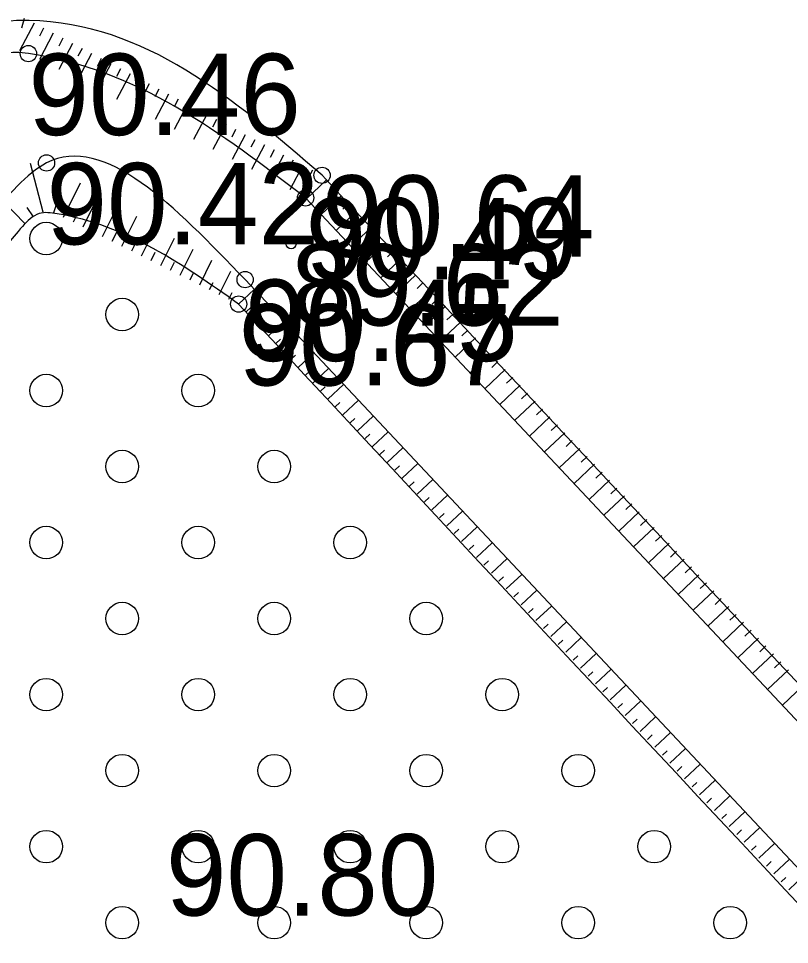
# Model space of a CAD drawing. Extents: x 316000 to 728450, y 314368 to 726000.
# Drawn here: x 725730.72 to 725766.23, y 315597.5 to 315640.13 of the extents above; entities that cross this region are included whole.
import ezdxf

# ---------------------------------------------------------------- set-up
doc = ezdxf.new("R2010")
doc.units = 0
for name, color, linetype in [('HIDG_ELEM_####_####_#', 7, 'Continuous'), ('HIDG_GRAV_####_####_#', 7, 'Continuous'), ('RELJ_AATZ_####_TKST_#', 7, 'Continuous'), ('RELJ_ELEM_####_####_#', 7, 'Continuous'), ('RELJ_NOGA_####_####_#', 7, 'Continuous'), ('TERT_ELEM_####_####_#', 7, 'Continuous')]:
    doc.layers.add(name, color=color, linetype=linetype)

msp = doc.modelspace()

# ---------------------------------------------------------------- linework, layer by layer
at = {"layer": 'HIDG_ELEM_####_####_#'}
msp.add_circle((725743.279, 315629.745), 0.225, dxfattribs=at)
at = {"layer": 'HIDG_GRAV_####_####_#'}
for points in [[(726259.175, 315086.515), (726260.768, 315088.859), (726179.005, 315175.766), (726127.8590000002, 315229.05600000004), (726063.0550000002, 315296.073), (725998.338, 315364.31700000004), (725936.648, 315430.32), (725875.3450000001, 315494.08300000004), (725809.436, 315562.19200000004), (725743.944, 315631.872)], [(725741.1610000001, 315628.109), (725806.0620000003, 315558.993), (725870.895, 315491.87100000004), (725934.12, 315427.077), (725995.775, 315361.63200000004), (726059.846, 315293.396), (726126.03, 315226.728), (726194.4910000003, 315154.86), (726259.1750000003, 315086.515)]]:
    msp.add_lwpolyline(points, dxfattribs=at)
for points in [[(725743.944, 315631.872), (725731.1800000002, 315638.5140000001), (725730.0588248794, 315638.4860084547), (725729.0416291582, 315637.5281018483), (725728.0741186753, 315636.1890738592), (725727.1019992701, 315635.017718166), (725611.6787771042, 315529.82054677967)], [(725741.1610000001, 315628.109), (725732.013, 315633.48000000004), (725729.3674430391, 315630.93907173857), (725612.6699933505, 315527.51301727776), (725555.2138402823, 315474.3075427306)]]:
    msp.add_spline(points, degree=3, dxfattribs=at)
at = {"layer": 'RELJ_ELEM_####_####_#'}
for centre in [(725731.18, 315638.514), (725732.013, 315633.48000000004), (725744.701, 315632.911), (725743.944, 315631.87200000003), (725741.1610000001, 315628.109), (725740.8620000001, 315626.984)]:
    msp.add_circle(centre, 0.375, dxfattribs=at)
at = {"layer": 'RELJ_NOGA_####_####_#'}
for p, q in [((725731.4387330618, 315639.91901510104), (725730.7655485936, 315638.6450520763)), ((725730.9867285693, 315640.1303772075), (725730.8541698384, 315639.6851369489)), ((725732.3228841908, 315639.4518140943), (725731.6877181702, 315638.24979880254)), ((725731.8808086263, 315639.6854145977), (725731.6898164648, 315639.3239728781)), ((725733.2070353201, 315638.98461308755), (725732.5748183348, 315637.7881786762)), ((725732.7649597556, 315639.2182135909), (725732.5748523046, 315638.8584461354)), ((725733.6491108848, 315638.7510125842), (725733.4598881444, 315638.39291939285)), ((725734.0911864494, 315638.51741208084), (725733.4619184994, 315637.32655854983)), ((725734.5332620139, 315638.2838115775), (725734.3449239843, 315637.9273926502)), ((725734.9753375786, 315638.05021107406), (725734.349018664, 315636.8649384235)), ((725735.4174131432, 315637.8166105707), (725735.2299598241, 315637.46186590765)), ((725735.8594887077, 315637.5830100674), (725735.2361188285, 315636.40331829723)), ((725736.3015642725, 315637.349409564), (725736.114995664, 315636.99633916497)), ((725736.743639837, 315637.11580906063), (725736.1232189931, 315635.94169817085)), ((725737.1857154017, 315636.8822085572), (725737.0000315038, 315636.5308124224)), ((725737.6277909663, 315636.6486080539), (725737.0103191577, 315635.4800780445)), ((725738.0698665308, 315636.41500755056), (725737.8850673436, 315636.06528567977)), ((725738.5119420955, 315636.18140704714), (725737.8974193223, 315635.01845791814)), ((725738.9540176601, 315635.9478065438), (725738.7701031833, 315635.59975893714)), ((725739.3960932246, 315635.7142060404), (725738.7845194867, 315634.55683779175)), ((725739.8381687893, 315635.4806055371), (725739.6551390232, 315635.1342321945)), ((725740.2802443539, 315635.2470050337), (725739.6716196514, 315634.0952176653)), ((725740.7223199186, 315635.0134045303), (725740.5401748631, 315634.6687054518)), ((725741.1643954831, 315634.77980402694), (725740.5587198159, 315633.63359753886)), ((725741.6064710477, 315634.5462035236), (725741.4252107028, 315634.20317870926)), ((725742.0485466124, 315634.3126030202), (725741.4458199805, 315633.1719774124)), ((725742.490622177, 315634.07900251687), (725742.3102465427, 315633.73765196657)), ((725742.9326977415, 315633.84540201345), (725742.3329201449, 315632.71035728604)), ((725731.8567331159, 315631.2111052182), (725731.2755291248, 315633.45294873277)), ((725743.3747733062, 315633.6118015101), (725743.1952823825, 315633.27212522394)), ((725743.8168488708, 315633.37820100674), (725743.2200203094, 315632.2487371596)), ((725744.2589244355, 315633.1446005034), (725744.0803182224, 315632.80659848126)), ((725732.8026071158, 315630.98976913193), (725733.5823610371, 315632.5585922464)), ((725744.9022320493, 315632.6976989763), (725743.983013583, 315631.8304916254)), ((725744.701, 315632.911), (725744.700532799, 315632.9101158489)), ((725745.2453464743, 315632.33400612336), (725744.9693772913, 315632.07365179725)), ((725731.0255166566, 315630.67487591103), (725729.9985763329, 315631.7343684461)), ((725732.349991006, 315631.20106889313), (725732.5172724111, 315631.72717694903)), ((725733.6980952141, 315630.5446836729), (725734.4468087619, 315632.05105521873)), ((725745.5884608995, 315631.9703132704), (725744.667884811, 315631.10182511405)), ((725731.40845525, 315630.9954562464), (725731.1165945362, 315631.4271271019)), ((725733.250351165, 315630.7672264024), (725733.4796212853, 315631.22850560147)), ((725734.5935833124, 315630.0995982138), (725735.3112564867, 315631.5435181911)), ((725746.2746897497, 315631.2429275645), (725745.3527560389, 315630.37315860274)), ((725745.9315753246, 315631.60662041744), (725745.6551988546, 315631.3458818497)), ((725735.4890714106, 315629.6545127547), (725736.1757042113, 315631.03598116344)), ((725746.6178041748, 315630.8792347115), (725746.3410204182, 315630.6181119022)), ((725734.1458392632, 315630.3221409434), (725734.3657972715, 315630.7646846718)), ((725736.3845595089, 315629.2094272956), (725737.040151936, 315630.52844413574)), ((725746.9609185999, 315630.51554185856), (725746.0376272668, 315629.6444920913)), ((725735.0413273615, 315629.8770554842), (725735.2519732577, 315630.30086374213)), ((725737.280047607, 315628.76434183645), (725737.9045996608, 315630.020907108)), ((725747.3040330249, 315630.15184900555), (725747.0268419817, 315629.89034195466)), ((725735.9368154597, 315629.4319700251), (725736.138149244, 315629.83704281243)), ((725747.64714745, 315629.7881561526), (725746.7224984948, 315628.91582558)), ((725736.832303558, 315628.986884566), (725737.0243252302, 315629.3732218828)), ((725738.1755357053, 315628.3192563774), (725738.7690473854, 315629.51337008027)), ((725747.9902618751, 315629.4244632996), (725747.7126635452, 315629.16257200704)), ((725737.7277916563, 315628.5417991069), (725737.9105012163, 315628.9094009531)), ((725739.0710238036, 315627.87417091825), (725739.6334951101, 315629.00583305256)), ((725748.3333763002, 315629.06077044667), (725747.4073697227, 315628.18715906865)), ((725748.6764907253, 315628.6970775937), (725748.3984851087, 315628.4348020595)), ((725738.6232797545, 315628.0967136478), (725738.7966772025, 315628.4455800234)), ((725739.9665119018, 315627.42908545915), (725740.4979428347, 315628.49829602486)), ((725749.0196051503, 315628.33338474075), (725748.0922409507, 315627.4584925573)), ((725739.5187678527, 315627.6516281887), (725739.6828531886, 315627.9817590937)), ((725749.3627195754, 315627.9696918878), (725749.0843066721, 315627.70703211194)), ((725740.414255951, 315627.2065427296), (725740.5690291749, 315627.517938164)), ((725740.8620000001, 315626.984), (725741.5822104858, 315627.66043396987)), ((725749.7058340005, 315627.60599903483), (725748.7771121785, 315626.7298260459)), ((725740.8620000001, 315626.984), (725740.8624450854, 315626.98489548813)), ((725750.0489484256, 315627.2423061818), (725749.7701282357, 315626.9792621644)), ((725741.204303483, 315626.6195437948), (725741.4203549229, 315626.8224629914)), ((725741.5466069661, 315626.25508758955), (725742.2667394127, 315626.93144826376)), ((725750.3920628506, 315626.87861332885), (725749.4619834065, 315626.00115953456)), ((725742.2312139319, 315625.52617517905), (725742.9512683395, 315626.20246255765)), ((725751.0782917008, 315626.15122762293), (725750.1468546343, 315625.27249302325)), ((725750.7351772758, 315626.51492047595), (725750.4559497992, 315626.25149221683)), ((725741.888910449, 315625.89063138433), (725742.104938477, 315626.09352859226)), ((725751.4214061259, 315625.78753477), (725751.1417713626, 315625.5237222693)), ((725742.573517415, 315625.16171897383), (725742.7895220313, 315625.3645941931)), ((725742.915820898, 315624.7972627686), (725743.6357972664, 315625.4734768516)), ((725751.764520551, 315625.423841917), (725750.8317258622, 315624.54382651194)), ((725752.107634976, 315625.06014906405), (725751.8275929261, 315624.79595232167)), ((725743.258124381, 315624.4328065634), (725743.4741055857, 315624.6356597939)), ((725743.6004278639, 315624.06835035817), (725744.3203261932, 315624.7444911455)), ((725752.4507494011, 315624.69645621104), (725751.5165970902, 315623.8151600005)), ((725744.28503483, 315623.33943794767), (725745.0048551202, 315624.01550543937)), ((725752.7938638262, 315624.3327633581), (725752.5134144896, 315624.0681823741)), ((725743.9427313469, 315623.70389415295), (725744.1586891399, 315623.9067253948)), ((725753.1369782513, 315623.9690705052), (725752.2014683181, 315623.0864934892)), ((725753.4800926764, 315623.60537765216), (725753.1992360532, 315623.34041242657)), ((725744.6273383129, 315622.97498174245), (725744.8432726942, 315623.1777909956)), ((725744.969641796, 315622.6105255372), (725745.6893840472, 315623.28651973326)), ((725753.8232071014, 315623.2416847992), (725752.8863395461, 315622.35782697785)), ((725754.1663215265, 315622.87799194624), (725753.8850576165, 315622.612642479)), ((725745.3119452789, 315622.246069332), (725745.5278562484, 315622.4488565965)), ((725745.6542487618, 315621.8816131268), (725746.373912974, 315622.55753402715)), ((725754.5094359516, 315622.5142990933), (725753.571210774, 315621.6291604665)), ((725754.8525503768, 315622.15060624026), (725754.5708791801, 315621.8848725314)), ((725745.9965522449, 315621.51715692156), (725746.2124398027, 315621.7199221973)), ((725746.3388557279, 315621.1527007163), (725747.058441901, 315621.82854832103)), ((725755.1956648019, 315621.7869133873), (725754.256082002, 315620.9004939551)), ((725755.538779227, 315621.4232205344), (725755.2567007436, 315621.1571025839)), ((725747.0234626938, 315620.42378830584), (725747.7429708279, 315621.099562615)), ((725755.881893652, 315621.05952768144), (725754.9409532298, 315620.17182744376)), ((725746.6811592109, 315620.78824451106), (725746.897023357, 315620.99098779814)), ((725756.2250080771, 315620.6958348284), (725755.942522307, 315620.4293326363)), ((725747.3657661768, 315620.0593321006), (725747.5816069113, 315620.262053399)), ((725747.7080696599, 315619.6948758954), (725748.4274997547, 315620.37057690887)), ((725756.5681225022, 315620.33214197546), (725755.6258244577, 315619.4431609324)), ((725756.9112369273, 315619.9684491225), (725756.6283438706, 315619.70156268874)), ((725748.0503731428, 315619.3304196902), (725748.2661904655, 315619.53311899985)), ((725748.3926766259, 315618.9659634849), (725749.1120286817, 315619.64159120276)), ((725757.2543513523, 315619.60475626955), (725756.3106956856, 315618.71449442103)), ((725749.0772835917, 315618.23705107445), (725749.7965576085, 315618.91260549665)), ((725757.9405802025, 315618.8773705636), (725756.9955669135, 315617.9858279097)), ((725757.5974657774, 315619.2410634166), (725757.3141654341, 315618.9737927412)), ((725748.7349801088, 315618.6015072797), (725748.9507740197, 315618.8041846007)), ((725758.2836946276, 315618.51367771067), (725757.9999869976, 315618.2460227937)), ((725749.4195870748, 315617.8725948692), (725749.635357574, 315618.0752502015)), ((725749.7618905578, 315617.50813866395), (725750.4810865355, 315618.1836197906)), ((725758.6268090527, 315618.14998485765), (725757.6804381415, 315617.25716139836)), ((725758.9699234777, 315617.7862920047), (725758.685808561, 315617.5182528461)), ((725750.1041940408, 315617.1436824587), (725750.3199411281, 315617.3463158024)), ((725750.4464975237, 315616.7792262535), (725751.1656154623, 315617.45463408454)), ((725759.3130379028, 315617.42259915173), (725758.3653093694, 315616.528494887)), ((725759.656152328, 315617.0589062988), (725759.3716301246, 315616.79048289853)), ((725750.7888010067, 315616.4147700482), (725751.0045246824, 315616.61738140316)), ((725751.1311044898, 315616.050313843), (725751.8501443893, 315616.7256483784)), ((725759.9992667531, 315616.6952134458), (725759.0501805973, 315615.79982837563)), ((725760.3423811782, 315616.33152059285), (725760.057451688, 315616.062712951)), ((725751.4734079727, 315615.6858576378), (725751.6891082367, 315615.888447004)), ((725751.8157114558, 315615.32140143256), (725752.5346733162, 315615.99666267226)), ((725760.6854956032, 315615.9678277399), (725759.7350518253, 315615.07116186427)), ((725761.0286100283, 315615.6041348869), (725760.7432732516, 315615.3349430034)), ((725752.1580149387, 315614.95694522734), (725752.3736917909, 315615.15951260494)), ((725752.5003184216, 315614.5924890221), (725753.219202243, 315615.2676769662)), ((725761.3717244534, 315615.2404420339), (725760.4199230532, 315614.34249535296)), ((725761.7148388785, 315614.87674918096), (725761.429094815, 315614.6071730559)), ((725752.8426219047, 315614.22803281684), (725753.0582753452, 315614.43057820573)), ((725753.1849253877, 315613.8635766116), (725753.9037311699, 315614.53869126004)), ((725762.0579533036, 315614.51305632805), (725761.1047942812, 315613.6138288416)), ((725753.8695323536, 315613.1346642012), (725754.5882600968, 315613.80970555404)), ((725762.7441821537, 315613.7856706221), (725761.789665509, 315612.88516233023)), ((725762.4010677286, 315614.14936347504), (725762.1149163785, 315613.8794031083)), ((725753.5272288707, 315613.4991204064), (725753.7428588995, 315613.7016438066)), ((725763.0872965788, 315613.4219777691), (725762.8007379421, 315613.15163316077)), ((725754.2118358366, 315612.77020799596), (725754.4274424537, 315612.97270940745)), ((725754.5541393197, 315612.40575179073), (725755.2727890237, 315613.0807198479)), ((725763.4304110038, 315613.05828491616), (725762.474536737, 315612.1564958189)), ((725763.773525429, 315612.69459206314), (725763.4865595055, 315612.42386321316)), ((725754.8964428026, 315612.04129558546), (725755.1120260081, 315612.24377500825)), ((725755.2387462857, 315611.67683938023), (725755.9573179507, 315612.35173414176)), ((725764.116639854, 315612.3308992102), (725763.1594079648, 315611.42782930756)), ((725755.9233532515, 315610.9479269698), (725756.6418468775, 315611.62274843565)), ((725764.4597542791, 315611.9672063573), (725764.172381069, 315611.69609326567)), ((725755.5810497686, 315611.312383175), (725755.7966095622, 315611.51484060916)), ((725764.8028687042, 315611.60351350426), (725763.8442791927, 315610.6991627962)), ((725765.1459831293, 315611.2398206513), (725764.8582026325, 315610.96832331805)), ((725756.2656567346, 315610.58347076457), (725756.4811931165, 315610.78590620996)), ((725756.6079602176, 315610.21901455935), (725757.3263758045, 315610.89376272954)), ((725765.4890975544, 315610.87612779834), (725764.5291504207, 315609.97049628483)), ((725765.8322119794, 315610.5124349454), (725765.544024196, 315610.2405533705)), ((725756.9502637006, 315609.85455835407), (725757.1657766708, 315610.05697181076)), ((725757.2925671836, 315609.49010214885), (725758.0109047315, 315610.1647770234)), ((725766.1753264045, 315610.14874209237), (725765.2140216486, 315609.24182977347)), ((725757.6348706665, 315609.1256459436), (725757.8503602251, 315609.3280374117)), ((725757.9771741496, 315608.7611897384), (725758.6954336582, 315609.4357913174)), ((725766.8615552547, 315609.4213563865), (725765.8988928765, 315608.51316326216)), ((725758.6617811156, 315608.03227732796), (725759.3799625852, 315608.7068056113)), ((725758.3194776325, 315608.3967335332), (725758.5349437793, 315608.5991030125)), ((725759.0040845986, 315607.6678211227), (725759.2195273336, 315607.8701686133)), ((725759.3463880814, 315607.30336491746), (725760.064491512, 315607.9778199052)), ((725759.6886915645, 315606.93890871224), (725759.9041108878, 315607.1412342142)), ((725760.0309950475, 315606.57445250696), (725760.749020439, 315607.24883419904)), ((725760.7156020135, 315605.8455400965), (725761.4335493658, 315606.5198484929)), ((725760.3732985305, 315606.20999630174), (725760.5886944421, 315606.41229981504)), ((725761.0579054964, 315605.4810838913), (725761.2732779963, 315605.6833654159)), ((725761.4002089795, 315605.116627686), (725762.1180782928, 315605.7908627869)), ((725761.7425124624, 315604.7521714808), (725761.9578615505, 315604.9544310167)), ((725762.0848159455, 315604.3877152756), (725762.8026072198, 315605.06187708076)), ((725762.4271194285, 315604.02325907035), (725762.6424451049, 315604.22549661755)), ((725762.7694229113, 315603.65880286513), (725763.4871361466, 315604.3328913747)), ((725763.4540298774, 315602.92989045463), (725764.1716650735, 315603.60390566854)), ((725763.1117263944, 315603.2943466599), (725763.327028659, 315603.49656221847)), ((725763.7963333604, 315602.5654342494), (725764.0116122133, 315602.7676278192)), ((725764.1386368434, 315602.2009780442), (725764.8561940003, 315602.8749199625)), ((725764.4809403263, 315601.83652183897), (725764.6961957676, 315602.03869342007)), ((725764.8232438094, 315601.47206563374), (725765.5407229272, 315602.1459342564)), ((725765.5078507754, 315600.74315322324), (725766.2252518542, 315601.41694855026)), ((725765.1655472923, 315601.1076094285), (725765.3807793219, 315601.309759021)), ((725765.8501542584, 315600.378697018), (725766.0653628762, 315600.5808246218)), ((725766.1924577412, 315600.0142408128), (725766.9097807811, 315600.6879628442))]:
    msp.add_line(p, q, dxfattribs=at)
for points in [[(725744.701, 315632.911), (725731.2122469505, 315640.0386943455), (725729.056271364, 315639.5840256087), (725728.3072907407, 315638.79600724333), (725727.6980921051, 315637.94217499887), (725727.1090350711, 315637.09598736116), (725726.4204792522, 315636.33090281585), (725610.4090988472, 315531.96836123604)], [(726259.1175937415, 315084.507430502), (726262.723, 315089.259), (726261.5614604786, 315090.83709791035), (726260.2047886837, 315092.42030988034), (726257.2926694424, 315095.5321723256), (726218.9119614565, 315136.38322796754), (726180.307, 315176.838), (726128.672, 315229.97), (726063.701, 315298.11), (725999.895, 315366.09400000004), (725937.206, 315432.091), (725876.347, 315495.232), (725810.578, 315563.08300000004), (725744.701, 315632.911)], [(725740.8620000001, 315626.984), (725732.496455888, 315631.1419358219), (725731.675729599, 315631.1475109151), (725730.9005735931, 315630.5492934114), (725730.162049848, 315629.6870659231), (725729.4512203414, 315628.90061106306), (725614.9961785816, 315525.0175506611)], [(725740.8620000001, 315626.984), (725805.544, 315558.11600000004), (725870.385, 315491.147), (725932.8030000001, 315426.796), (725994.9770000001, 315360.836), (726059.6610000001, 315292.118), (726075.7456892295, 315275.45786653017), (726092.0847165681, 315259.0432961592), (726108.4698856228, 315242.67257770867), (726124.6930000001, 315226.144), (726193.2690000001, 315154.025), (726250.0620111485, 315092.59955891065), (726256.3184263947, 315085.82961944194), (726258.824, 315084.289), (726259.1175937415, 315084.507430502)]]:
    msp.add_spline(points, degree=3, dxfattribs=at)
at = {"layer": 'TERT_ELEM_####_####_#'}
for centre in [(725732, 315630), (725735.5, 315626.5), (725732, 315623), (725739, 315623), (725735.5, 315619.5), (725742.5, 315619.5), (725732, 315616), (725739, 315616), (725746, 315616), (725735.5, 315612.5), (725742.5, 315612.5), (725749.5, 315612.5), (725732, 315609), (725739, 315609), (725746, 315609), (725753, 315609), (725735.5, 315605.5), (725742.5, 315605.5), (725749.5, 315605.5), (725756.5, 315605.5), (725732, 315602), (725739, 315602), (725746, 315602), (725753, 315602), (725760, 315602), (725735.5, 315598.5), (725742.5, 315598.5), (725749.5, 315598.5), (725756.5, 315598.5), (725763.5, 315598.5)]:
    msp.add_circle(centre, 0.75, dxfattribs=at)

# ---------------------------------------------------------------- texts
at = {"layer": 'RELJ_AATZ_####_TKST_#'}
for s, p in [('90.46', (725731.18, 315634.764)), ('90.42', (725732.013, 315629.73000000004)), ('90.64', (725744.701, 315629.161)), ('90.49', (725743.944, 315628.12200000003)), ('89.62', (725743.279, 315625.995)), ('90.45', (725741.1610000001, 315624.359)), ('90.67', (725740.8620000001, 315623.234)), ('90.80', (725737.512, 315598.82800000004))]:
    msp.add_text(s, height=3.75, dxfattribs=at).set_placement(p)

doc.saveas('drawing.dxf')
